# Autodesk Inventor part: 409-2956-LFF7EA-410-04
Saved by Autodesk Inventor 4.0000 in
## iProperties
Created: 2010-06
Part Number: 409-2956-LFF7EA-410-04
Cost Center: 0 lbmass
Material: A304 STAINLESS STEEL
Document SubType Name: Sheet Metal
Designer: S. Boerckel
Authority: 0 in^3
Mass: 155.751 g
Surface Area: 164.242 cm^2
Volume: 19.2761 cm^3
Density: 8.08 g/cm^3
Flat Pattern Width: 10.16 cm
Flat Pattern Length: 10.16 cm
Flat Pattern Area: 103.226 cm^2
Sheet Metal Rule: 12Ga
Sheet Metal Width: 4.0000 in
Sheet Metal Length: 16.0000 in^2
Description: STRAINER SHIM
User Status: BURN
SaveDate: 2008-01-15
SaveTime: 10:24
FileName: Sheet Metal
Wide: =<Flat Pattern Width>cm
Length: =<Flat Pattern Length>cm
Thickness: 0.1046 in
SMR: =<Sheet Metal Rule> - <Material>
Author: S. Boerckel
Revision Number: 0
Title: STRAINER 18Ga SHIM
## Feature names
1. Plate1
2. Cut1
